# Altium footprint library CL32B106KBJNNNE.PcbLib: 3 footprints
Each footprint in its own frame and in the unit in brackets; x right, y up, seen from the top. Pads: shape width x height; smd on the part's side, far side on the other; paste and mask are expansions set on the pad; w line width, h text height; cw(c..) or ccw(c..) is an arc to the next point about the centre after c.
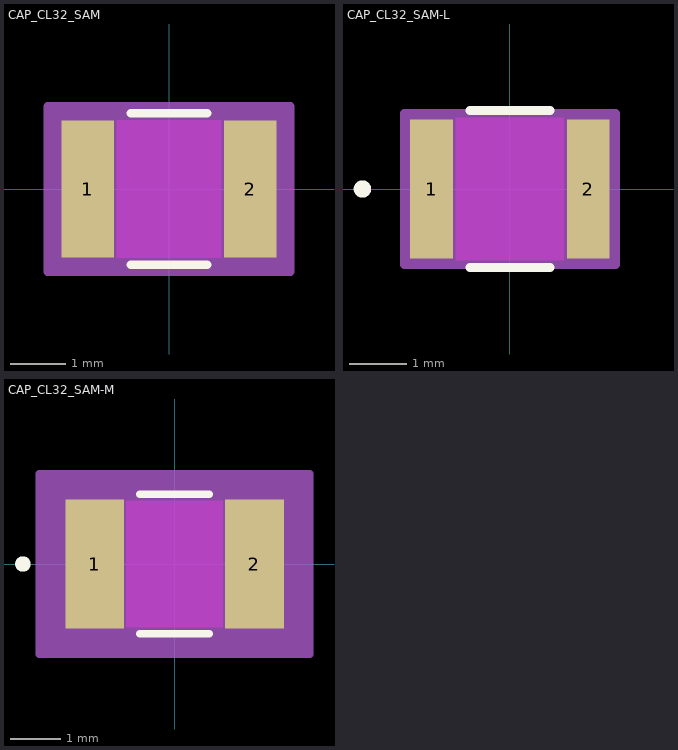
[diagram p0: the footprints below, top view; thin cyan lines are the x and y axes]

## CAP_CL32_SAM [mm]
pads (2):
  rect 0.956x2.5 smd paste+0 mask+0: 1(-1.478,0) 2(1.478,0)
Top Layer keep-out:
  region: -0.949,-1.199 -0.949,1.199 0.949,1.199 0.949,-1.199
Top Overlay:
  lines w0.152: -0.692,-1.377 0.692,-1.377 ; -0.692,1.377 0.692,1.377
Keep-Out Layer:
  region: -0.949,-1.25 -0.949,1.25 0.949,1.25 0.949,-1.25
Mechanical 13:
  circle w0: c-1.351,0 r0
  lines w0.025: -1.6,-1.25 -1.6,1.25 ; -1.6,-1.25 -1,-1.25 -1,1.25 -1.6,1.25 ; -1.6,-1.25 1.6,-1.25 ; -1.6,-1.25 -1.6,1.25 ; -1.6,1.25 1.6,1.25 ; 1.6,-1.25 1,-1.25 1,1.25 1.6,1.25 ; 1.6,-1.25 1.6,1.25 ; 1.6,-1.25 1.6,1.25
Mechanical 15:
  region: 2.21,-1.504 -2.21,-1.504 -2.21,1.504 2.21,1.504
  lines w0.152: -2.21,-1.504 -2.21,1.504 2.21,1.504 2.21,-1.504 -2.21,-1.504
3D body "CAP_CL32_SAM.step": height 1, standoff 0, extent -1.6,-1.25 1.6,1.25

## CAP_CL32_SAM-L [mm]
pads (2):
  rect 0.752x2.449 smd paste+0 mask+0: 1(-1.376,0) 2(1.376,0)
Top Layer keep-out:
  region: -0.949,-1.199 -0.949,1.199 0.949,1.199 0.949,-1.199
Top Overlay:
  circle w0.152: c-2.591,0 r0.076
  lines w0.152: -0.704,-1.377 0.704,-1.377 ; -0.704,1.377 0.704,1.377
Keep-Out Layer:
  region: -0.949,-1.25 -0.949,1.25 0.949,1.25 0.949,-1.25
Mechanical 13:
  circle w0: c-1.249,0 r0.076
  lines w0.025: -1.6,-1.25 -1.6,1.25 ; -1.6,-1.25 -1,-1.25 -1,1.25 -1.6,1.25 ; -1.6,-1.25 1.6,-1.25 ; -1.6,-1.25 -1.6,1.25 ; -1.6,1.25 1.6,1.25 ; 1.6,-1.25 1,-1.25 1,1.25 1.6,1.25 ; 1.6,-1.25 1.6,1.25 ; 1.6,-1.25 1.6,1.25
Mechanical 15:
  region: 1.854,-1.326 -1.854,-1.326 -1.854,1.326 1.854,1.326
  lines w0.152: -1.854,-1.326 -1.854,1.326 1.854,1.326 1.854,-1.326 -1.854,-1.326
3D body "CAP_CL32_SAM.step": height 1, standoff 0, extent -1.6,-1.25 1.6,1.25

## CAP_CL32_SAM-M [mm]
pads (2):
  rect 1.159x2.551 smd paste+0 mask+0: 1(-1.579,0) 2(1.579,0)
Top Layer keep-out:
  region: -0.949,-1.199 -0.949,1.199 0.949,1.199 0.949,-1.199
Top Overlay:
  circle w0.152: c-2.997,0 r0.076
  lines w0.152: -0.683,-1.377 0.683,-1.377 ; -0.683,1.377 0.683,1.377
Keep-Out Layer:
  region: -0.949,-1.25 -0.949,1.25 0.949,1.25 0.949,-1.25
Mechanical 13:
  circle w0: c-1.452,0 r0.076
  lines w0.025: -1.6,-1.25 -1.6,1.25 ; -1.6,-1.25 -1,-1.25 -1,1.25 -1.6,1.25 ; -1.6,-1.25 1.6,-1.25 ; -1.6,-1.25 -1.6,1.25 ; -1.6,1.25 1.6,1.25 ; 1.6,-1.25 1,-1.25 1,1.25 1.6,1.25 ; 1.6,-1.25 1.6,1.25 ; 1.6,-1.25 1.6,1.25
Mechanical 15:
  region: 2.667,-1.783 -2.667,-1.783 -2.667,1.783 2.667,1.783
  lines w0.152: -2.667,-1.783 -2.667,1.783 2.667,1.783 2.667,-1.783 -2.667,-1.783
3D body "CAP_CL32_SAM.step": height 1, standoff 0, extent -1.6,-1.25 1.6,1.25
